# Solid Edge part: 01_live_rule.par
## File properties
Author: edge
Template: sync jis part.par
Last saved by: edge
Revision: 3
Application: Solid Edge
文書内容のタイプ: 0
Accuracy: 0.990
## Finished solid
Body 1: solid body, 16 faces, 36 edges, 20 vertices.
  Faces by surface: plane 10, cylinder 6
  Edges by curve: line 24, circle 12
Bounding box of the edges (mm): 108.625 x 91.688 x 9.525, from (-12.2852, 0, 0) to (96.3395, 91.688, 9.525).
Cylindrical faces by radius (mm): R4.765 x2, R7.025 x1, R12.7 x2, R25.4 x1
Planar faces by outward normal: +z 2, -y 1, -z 1, oblique 6
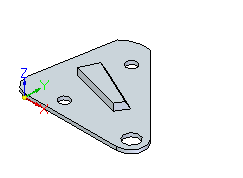
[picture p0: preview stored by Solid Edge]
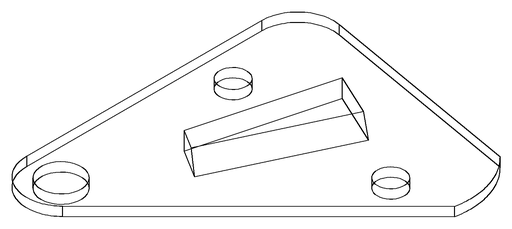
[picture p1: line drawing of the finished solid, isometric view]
